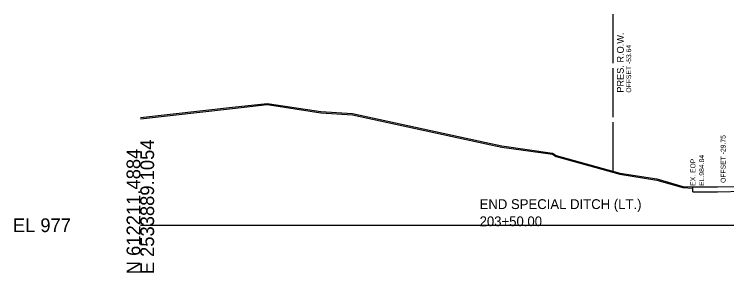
# Model space of a CAD drawing. Extents: x -120 to 2876, y -25 to 8560.
# Drawn here: x -25.7 to 119.5, y 6490.3 to 6543 of the extents above; entities that cross this region are included whole.
import ezdxf

# ---------------------------------------------------------------- set-up
doc = ezdxf.new("R2010")
doc.units = 0
for name, color, linetype in [('DESIGN - SHEET - Light Grid', 7, 'Continuous'), ('DESIGN - TRANSPORTATION - Text', 7, 'Continuous'), ('DESIGN - TYPICAL - Slope Tie Text', 7, 'Continuous'), ('SURVEY - GROUND - Bottom of Topsoil Layer', 7, 'Continuous'), ('SURVEY - GROUND - Existing Pavement Layer', 7, 'Continuous'), ('SURVEY - GROUND - Existing Pavement Text', 7, 'Continuous'), ('SURVEY - GROUND - Top of Ground', 7, 'Continuous'), ('SURVEY - PROPERTY - ROW Lines', 7, 'Continuous'), ('SURVEY - PROPERTY - ROW Lines Text', 7, 'Continuous')]:
    doc.layers.add(name, color=color, linetype=linetype)

msp = doc.modelspace()

# ---------------------------------------------------------------- linework, layer by layer
at = {"layer": 'DESIGN - SHEET - Light Grid'}
msp.add_line((0, 6500), (150, 6500), dxfattribs=at)
at = {"layer": 'SURVEY - GROUND - Bottom of Topsoil Layer'}
for p, q in [((18.78, 6523.82), (25.82, 6524.6)), ((25.82, 6524.6), (26.35, 6524.53)), ((26.35, 6524.53), (36.8, 6522.91)), ((0, 6521.73), (18.78, 6523.82)), ((36.8, 6522.91), (43.21, 6522.5)), ((43.21, 6522.5), (70.48, 6516.62)), ((70.48, 6516.62), (73.65, 6515.95)), ((73.65, 6515.95), (83.95, 6514.47)), ((83.95, 6514.47), (84.7, 6514)), ((84.7, 6514), (97.71, 6510.4)), ((97.71, 6510.4), (105.25, 6509.2)), ((105.25, 6509.2), (110.53, 6507.66)), ((110.53, 6507.66), (112.6, 6507.59)), ((112.6, 6507.59), (112.6, 6507.84))]:
    msp.add_line(p, q, dxfattribs=at)
at = {"layer": 'SURVEY - GROUND - Existing Pavement Layer'}
for p, q in [((112.6, 6506.84), (112.6, 6507.84)), ((112.6, 6506.84), (117.57, 6506.83)), ((117.57, 6506.83), (122.94, 6506.93))]:
    msp.add_line(p, q, dxfattribs=at)
at = {"layer": 'SURVEY - GROUND - Top of Ground'}
msp.add_lwpolyline([(0, 6521.98), (18.78, 6524.07), (25.82, 6524.85), (26.35, 6524.78), (36.8, 6523.16), (43.21, 6522.75), (70.48, 6516.87), (73.65, 6516.2), (83.95, 6514.72), (84.7, 6514.25), (97.71, 6510.65), (105.25, 6509.45), (110.53, 6507.91), (112.6, 6507.84), (117.57, 6507.83), (122.94, 6507.93)], dxfattribs=at)
at = {"layer": 'SURVEY - PROPERTY - ROW Lines'}
for p, q in [((96.36, 6533.03), (96.36, 6543.03)), ((96.36, 6522.03), (96.36, 6532.03)), ((96.36, 6511.03), (96.36, 6521.03))]:
    msp.add_line(p, q, dxfattribs=at)

# ---------------------------------------------------------------- texts
at = {"layer": 'DESIGN - SHEET - Light Grid'}
for s, p in [('E 2533889.1054', (2.8, 6490)), ('N 612211.4884', (0, 6490))]:
    msp.add_text(s, height=2.8, rotation=90, dxfattribs=at).set_placement(p)
msp.add_text('EL 977', height=2.8, dxfattribs=at).set_placement((-26, 6498.6))
at = {"layer": 'DESIGN - TRANSPORTATION - Text'}
for s, p in [('END SPECIAL DITCH (LT.)', (69.13, 6503.3)), ('203+50.00', (69.13, 6499.8))]:
    msp.add_text(s, height=2, dxfattribs=at).set_placement(p)
at = {"layer": 'DESIGN - TYPICAL - Slope Tie Text'}
msp.add_text('OFFSET -29.75', height=1, rotation=90, dxfattribs=at).set_placement((119.25, 6508.63))
at = {"layer": 'SURVEY - GROUND - Existing Pavement Text'}
for s, p in [('EX. EOP', (113.1, 6508.04)), ('EL.984.84', (114.87, 6508.04))]:
    msp.add_text(s, height=1, rotation=90, dxfattribs=at).set_placement(p)
at = {"layer": 'SURVEY - PROPERTY - ROW Lines Text'}
for s, height, p in [('PRES. R.O.W.', 1.4, (98.51, 6527.03)), ('OFFSET -53.64', 1, (100.01, 6527.03))]:
    msp.add_text(s, height=height, rotation=90, dxfattribs=at).set_placement(p)

doc.saveas('drawing.dxf')
